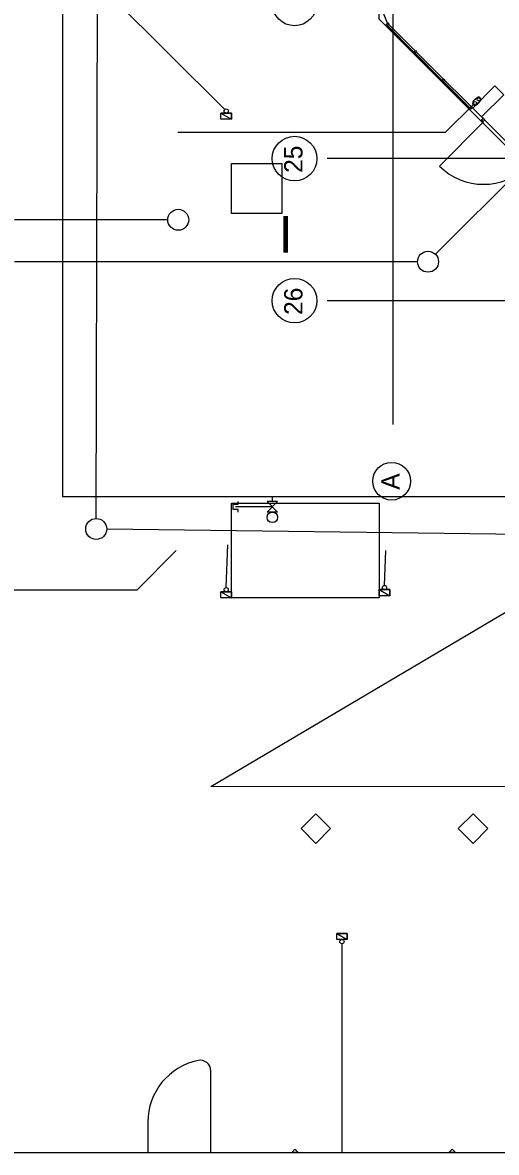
# Model space of a CAD drawing. Extents: x -264031 to -263588, y -1242281 to -1242059.
# Drawn here: x -263926.1 to -263903.5, y -1242281.4 to -1242227.5 of the extents above; entities that cross this region are included whole.
import ezdxf

# ---------------------------------------------------------------- set-up
doc = ezdxf.new("R2010")
doc.units = 0
for name, color, linetype in [('HESCON_OSI_STAVBY_KFA', 7, 'Continuous'), ('KFA_2D_SITUACIA_DSP', 7, 'Continuous'), ('KFA_JESTV_IS_DSP_-_KANAL_SPLASK', 7, 'Continuous'), ('RAM_NA_TLAC_3xA4_1-750', 7, 'Continuous')]:
    doc.layers.add(name, color=color, linetype=linetype)

msp = doc.modelspace()

# ---------------------------------------------------------------- linework, layer by layer
at = {"layer": 'HESCON_OSI_STAVBY_KFA'}
for p, q in [((-263908.393, -1242083.237), (-263908.393, -1242246.707)), ((-263792.653, -1242234.032), (-263911.523, -1242234.032)), ((-263792.653, -1242240.807), (-263911.523, -1242240.807))]:
    msp.add_line(p, q, dxfattribs=at)
for centre, radius in [((-263913.085, -1242226.632), 1.064), ((-263913.085, -1242234.032), 1.064), ((-263913.085, -1242240.807), 1.064), ((-263908.453, -1242249.416), 0.899)]:
    msp.add_circle(centre, radius, dxfattribs=at)
at = {"layer": 'KFA_2D_SITUACIA_DSP'}
for p, q in [((-263924.143, -1242185.14), (-263924.143, -1242250.14)), ((-263889.023, -1242221.253), (-263906.365, -1242238.596)), ((-263916.414, -1242231.691), (-263926.24, -1242221.865)), ((-263908.893, -1242226.995), (-263908.663, -1242227.55)), ((-263908.709, -1242227.631), (-263908.638, -1242227.56)), ((-263908.68, -1242227.659), (-263908.709, -1242227.631)), ((-263908.663, -1242227.55), (-263895.135, -1242241.078)), ((-263908.581, -1242227.617), (-263908.652, -1242227.688)), ((-263908.638, -1242227.56), (-263908.581, -1242227.617)), ((-263908.685, -1242227.654), (-263908.703, -1242227.672)), ((-263908.703, -1242227.672), (-263907.395, -1242228.98)), ((-263907.377, -1242228.963), (-263908.685, -1242227.654)), ((-263908.652, -1242227.688), (-263908.68, -1242227.659)), ((-263907.395, -1242228.98), (-263907.377, -1242228.963)), ((-263907.39, -1242228.95), (-263907.319, -1242228.879)), ((-263907.361, -1242228.978), (-263907.39, -1242228.95)), ((-263907.363, -1242229.012), (-263907.345, -1242228.994)), ((-263906.055, -1242230.32), (-263907.363, -1242229.012)), ((-263907.333, -1242229.007), (-263907.361, -1242228.978)), ((-263907.345, -1242228.994), (-263906.037, -1242230.303)), ((-263907.262, -1242228.936), (-263907.333, -1242229.007)), ((-263907.319, -1242228.879), (-263907.262, -1242228.936)), ((-263906.037, -1242230.303), (-263906.055, -1242230.32)), ((-263906.046, -1242230.294), (-263905.975, -1242230.223)), ((-263906.017, -1242230.322), (-263906.046, -1242230.294)), ((-263906.019, -1242230.356), (-263906.001, -1242230.338)), ((-263905.989, -1242230.351), (-263906.017, -1242230.322)), ((-263906.001, -1242230.338), (-263904.693, -1242231.647)), ((-263905.918, -1242230.28), (-263905.989, -1242230.351)), ((-263905.975, -1242230.223), (-263905.918, -1242230.28)), ((-263904.711, -1242231.664), (-263906.019, -1242230.356)), ((-263903.526, -1242230.561), (-263904.586, -1242231.622)), ((-263903.101, -1242230.985), (-263903.526, -1242230.561)), ((-263904.484, -1242231.218), (-263904.563, -1242231.296)), ((-263904.465, -1242231.218), (-263904.484, -1242231.218)), ((-263904.376, -1242231.13), (-263904.465, -1242231.218)), ((-263904.397, -1242231.462), (-263904.319, -1242231.383)), ((-263904.319, -1242231.383), (-263904.397, -1242231.462)), ((-263904.231, -1242231.275), (-263904.319, -1242231.364)), ((-263904.319, -1242231.364), (-263904.319, -1242231.383)), ((-263904.162, -1242232.046), (-263903.101, -1242230.985)), ((-263916.593, -1242231.862), (-263916.093, -1242231.862)), ((-263916.593, -1242232.152), (-263916.593, -1242231.862)), ((-263916.593, -1242231.862), (-263916.093, -1242232.152)), ((-263916.593, -1242231.862), (-263916.093, -1242232.152)), ((-263916.093, -1242231.862), (-263916.593, -1242231.862)), ((-263916.093, -1242231.862), (-263916.093, -1242232.152)), ((-263916.093, -1242232.152), (-263916.093, -1242231.862)), ((-263904.533, -1242231.432), (-263905.894, -1242232.793)), ((-263904.726, -1242231.613), (-263904.656, -1242231.543)), ((-263904.698, -1242231.642), (-263904.726, -1242231.613)), ((-263904.693, -1242231.647), (-263904.711, -1242231.664)), ((-263904.67, -1242231.67), (-263904.698, -1242231.642)), ((-263904.599, -1242231.599), (-263904.67, -1242231.67)), ((-263904.656, -1242231.543), (-263904.599, -1242231.599)), ((-263904.586, -1242231.622), (-263904.162, -1242232.046)), ((-263916.093, -1242232.152), (-263916.593, -1242232.152)), ((-263904.074, -1242232.281), (-263906.177, -1242234.384)), ((-263904.091, -1242232.093), (-263904.176, -1242232.178)), ((-263904.176, -1242232.178), (-263904.091, -1242232.263)), ((-263904.006, -1242232.178), (-263904.091, -1242232.093)), ((-263904.091, -1242232.263), (-263904.006, -1242232.178)), ((-263904.091, -1242232.263), (-263904.074, -1242232.281)), ((-263905.894, -1242232.793), (-263918.643, -1242232.793)), ((-263916.093, -1242234.257), (-263913.693, -1242234.257)), ((-263916.093, -1242236.657), (-263916.093, -1242234.257)), ((-263913.693, -1242234.257), (-263913.693, -1242236.657)), ((-263913.693, -1242236.657), (-263916.093, -1242236.657)), ((-263919.13, -1242236.949), (-263926.43, -1242236.949)), ((-263907.219, -1242238.949), (-263926.43, -1242238.949)), ((-263924.143, -1242250.14), (-263788.143, -1242250.14)), ((-263914.143, -1242250.14), (-263914.143, -1242250.39)), ((-263914.143, -1242250.14), (-263914.143, -1242250.39)), ((-263916.093, -1242254.982), (-263916.093, -1242250.458)), ((-263916.093, -1242250.458), (-263909.043, -1242250.458)), ((-263916.018, -1242250.515), (-263915.768, -1242250.515)), ((-263916.018, -1242250.765), (-263916.018, -1242250.515)), ((-263915.768, -1242250.765), (-263916.018, -1242250.765)), ((-263914.143, -1242250.64), (-263915.893, -1242250.64)), ((-263915.768, -1242250.515), (-263915.768, -1242250.39)), ((-263915.768, -1242250.89), (-263915.768, -1242250.765)), ((-263914.393, -1242250.39), (-263913.893, -1242250.89)), ((-263913.893, -1242250.39), (-263914.393, -1242250.39)), ((-263914.393, -1242250.89), (-263913.893, -1242250.39)), ((-263909.043, -1242250.458), (-263909.043, -1242254.982)), ((-263913.893, -1242250.89), (-263914.393, -1242250.89)), ((-263920.595, -1242254.592), (-263918.723, -1242252.72)), ((-263916.339, -1242254.492), (-263916.265, -1242252.443)), ((-263908.789, -1242254.387), (-263908.729, -1242252.715)), ((-263909.043, -1242254.587), (-263908.543, -1242254.587)), ((-263909.043, -1242254.877), (-263909.043, -1242254.587)), ((-263909.043, -1242254.587), (-263908.543, -1242254.877)), ((-263909.043, -1242254.587), (-263908.543, -1242254.877)), ((-263908.543, -1242254.587), (-263909.043, -1242254.587)), ((-263908.543, -1242254.587), (-263908.543, -1242254.877)), ((-263908.543, -1242254.877), (-263908.543, -1242254.587)), ((-263929.73, -1242254.592), (-263920.595, -1242254.592)), ((-263916.593, -1242254.692), (-263916.093, -1242254.692)), ((-263916.593, -1242254.982), (-263916.593, -1242254.692)), ((-263916.593, -1242254.692), (-263916.093, -1242254.982)), ((-263916.593, -1242254.692), (-263916.093, -1242254.982)), ((-263916.093, -1242254.692), (-263916.593, -1242254.692)), ((-263916.093, -1242254.982), (-263916.593, -1242254.982)), ((-263916.093, -1242254.692), (-263916.093, -1242254.982)), ((-263916.093, -1242254.982), (-263916.093, -1242254.692)), ((-263909.043, -1242254.982), (-263916.093, -1242254.982)), ((-263908.543, -1242254.877), (-263909.043, -1242254.877)), ((-263911.074, -1242270.983), (-263910.574, -1242270.983)), ((-263911.074, -1242271.273), (-263911.074, -1242270.983)), ((-263911.074, -1242270.983), (-263910.574, -1242271.273)), ((-263911.074, -1242270.983), (-263910.574, -1242271.273)), ((-263910.574, -1242270.983), (-263911.074, -1242270.983)), ((-263910.574, -1242271.273), (-263911.074, -1242271.273)), ((-263910.574, -1242270.983), (-263910.574, -1242271.273)), ((-263910.574, -1242271.273), (-263910.574, -1242270.983)), ((-263910.824, -1242271.473), (-263910.824, -1242281.427)), ((-263917.08, -1242281.427), (-263917.08, -1242277.533)), ((-263920.08, -1242279.982), (-263920.08, -1242281.427)), ((-263920.08, -1242281.427), (-263917.08, -1242281.427)), ((-263913.219, -1242281.427), (-263913.068, -1242281.275)), ((-263912.916, -1242281.427), (-263913.219, -1242281.427)), ((-263913.068, -1242281.275), (-263912.916, -1242281.427)), ((-263905.719, -1242281.427), (-263905.568, -1242281.275)), ((-263905.416, -1242281.427), (-263905.719, -1242281.427)), ((-263905.568, -1242281.275), (-263905.416, -1242281.427))]:
    msp.add_line(p, q, dxfattribs=at)
for points in [[(-263794.893, -1242227.382), (-263808.968, -1242241.457), (-263894.968, -1242241.457), (-263909.043, -1242227.382), (-263909.043, -1242196.333), (-263914.143, -1242196.333), (-263914.143, -1242132.433), (-263909.043, -1242132.433), (-263909.043, -1242101.382), (-263894.968, -1242087.307), (-263808.968, -1242087.307), (-263794.893, -1242101.382), (-263794.893, -1242227.382)], [(-263854.468, -1242263.985), (-263917.08, -1242263.982), (-263901.868, -1242254.982), (-263854.468, -1242254.985), (-263854.468, -1242263.985)]]:
    msp.add_lwpolyline(points, dxfattribs=at)
for points in [[(-263912.068, -1242265.279), (-263911.361, -1242265.986), (-263912.068, -1242266.693), (-263912.775, -1242265.986)], [(-263904.568, -1242265.279), (-263903.861, -1242265.986), (-263904.568, -1242266.693), (-263905.275, -1242265.986)]]:
    msp.add_lwpolyline(points, close=True, dxfattribs=at)
for centre, radius in [((-263904.48, -1242231.379), 0.075), ((-263904.303, -1242231.202), 0.075), ((-263916.343, -1242231.762), 0.1), ((-263918.63, -1242236.949), 0.5), ((-263906.719, -1242238.949), 0.5), ((-263914.143, -1242251.14), 0.25), ((-263916.343, -1242254.592), 0.1), ((-263908.793, -1242254.487), 0.1), ((-263910.824, -1242271.373), 0.1)]:
    msp.add_circle(centre, radius, dxfattribs=at)
for centre, radius, start, end in [((-263904.48, -1242231.379), 0.117, 135, 315), ((-263904.303, -1242231.202), 0.103, 315, 135), ((-263904.074, -1242232.281), 2.975, 225.0001, 315.0001), ((-263917.08, -1242279.982), 3, 101.537, 180), ((-263917.58, -1242277.533), 0.5, 0, 101.537)]:
    msp.add_arc(centre, radius, start, end, dxfattribs=at)
at = {"layer": 'KFA_JESTV_IS_DSP_-_KANAL_SPLASK'}
for p, q in [((-263922.54, -1242251.195), (-263922.477, -1242222.753)), ((-263877.504, -1242252.277), (-263922.041, -1242251.701))]:
    msp.add_line(p, q, dxfattribs=at)
msp.add_circle((-263922.541, -1242251.695), 0.5, dxfattribs=at)
at = {"layer": 'RAM_NA_TLAC_3xA4_1-750'}
msp.add_lwpolyline([(-264030.986, -1242281.427), (-263873.486, -1242281.427), (-263730.986, -1242281.427), (-263588.486, -1242281.427), (-263588.486, -1242058.677), (-263730.986, -1242058.677), (-263873.486, -1242058.677), (-264030.986, -1242058.677)], close=True, dxfattribs=at)

# ---------------------------------------------------------------- texts
at = {"layer": 'HESCON_OSI_STAVBY_KFA'}
for s, p in [('25', (-263912.704, -1242234.712)), ('26', (-263912.704, -1242241.487)), ('A', (-263908.072, -1242249.824))]:
    msp.add_text(s, height=0.875, rotation=90, dxfattribs=at).set_placement(p)
at = {"layer": 'KFA_2D_SITUACIA_DSP'}
msp.add_text('I', height=1.75, dxfattribs=at).set_placement((-263913.835, -1242238.519))

doc.saveas('drawing.dxf')
